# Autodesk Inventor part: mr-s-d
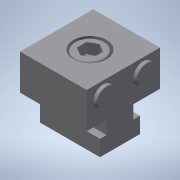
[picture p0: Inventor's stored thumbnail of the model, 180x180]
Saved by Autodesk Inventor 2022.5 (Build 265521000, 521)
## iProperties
Created: 2016-12
Part Number: mr-s-d
Material: 一般
Document SubType Name: Modeling
Designer: imaocorp
Density: 1 g/cm^3
Appearance: 既定
Author: imaocorp
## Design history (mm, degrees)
node "mr-s-d.x_t1"
node "mr-s-d"
node "Base1"
